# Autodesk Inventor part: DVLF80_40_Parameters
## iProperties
Created: 2010-03
Part Number: DVLF80_40_Parameters
Document SubType Name: Modeling
Designer: TB
Density: 1 g/cm^3
Slaglengde: 100.000 mm
Vinkel_Plussport: 0.00 deg
Vinkel_Minusport: 0.00 deg
Forlengelse_rør: 0.000 mm
Author: TB
